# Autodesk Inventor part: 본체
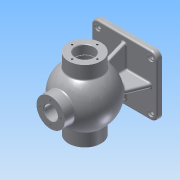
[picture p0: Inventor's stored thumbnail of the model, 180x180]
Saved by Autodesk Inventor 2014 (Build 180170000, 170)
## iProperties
Created: 2017-01
Part Number: 본체
Material: Aluminum 6061
Document SubType Name: Modeling
Designer: ksu
Density: 2.71 g/cm^3
Appearance: Aluminum - Flat
Mass: 1509 g
Surface Area: 1155.11 cm^2
Volume: 556.828 cm^3
Author: ksu
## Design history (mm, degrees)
sketch "Sketch1"
  geometry: L1 (-62.5, -57.5)-(62.5, -57.5); L2 (62.5, -57.5)-(62.5, 57.5); L3 (62.5, 57.5)-(-62.5, 57.5); L4 (-62.5, 57.5)-(-62.5, -57.5); L5 (-62.5, -57.5)-(62.5, 57.5); L6 (62.5, -57.5)-(-62.5, 57.5); 1 further point
  constraints: 12 end point, 2 midpoint, 2 parallel, 1 horizontal, 1 perpendicular
  dimensions: "d0" = 125 distance of L3.end L2.end; "d1" = 115 distance of L2.end L1.end
extrude "Extrusion1" new body sketch "Sketch1" distance "d2" = 10; taper "d3" = 0 deg
sketch "Sketch2"
  geometry: L1 (-57.5, 0)-(57.5, 0) reference; L2 (-68, 85)-(106.185, 85); L3 (-68, 116)-(-68, 102.5); L4 (68, 116)-(68, 102.5); L5 (-68, 116)-(-42.988, 116); L6 (42.988, 116)-(68, 116); L7 (-68, 102.5)-(-39.278, 102.5); L8 (39.278, 102.5)-(68, 102.5); A1 r 53 centre (0, 85) between (42.988, 116) and (-42.988, 116); A2 r 43 centre (0, 85) between (39.278, 102.5) and (-39.278, 102.5); 1 further point
  constraints: 14 end point, 6 parallel, 4 point on circle, 2 centre point, 1 coincident
  dimensions: "d4" = 106 diameter of A1; "d5" = 86 diameter of A2; "d6" = 85 distance from line of L1 A2.centre; "d9" = 136 distance of L3.start L4.start; "d10" = 68 horizontal distance of point (0, 0) L4.start; "d11" = 136 distance of L3.end L4.end; "d12" = 68 horizontal distance of point (0, 0) L4.end
revolve "Revolution1" sketch "Sketch2" stored, may be unused: angle "d13" = 90 deg
workplane "Work Plane1"
sketch "Sketch3"
  geometry: C1 r 27 at (0, 0); 1 further point
  constraints: 1 centre point, 1 coincident
  dimensions: "d15" = 54 diameter of C1
extrude "Extrusion2" join sketch "Sketch3" distance "d16" = 30; taper "d17" = 0 deg
sketch "Sketch4"
  geometry: C1 r 27 at (0, 0) reference; C2 r 13 at (0, 0)
  constraints: 1 centre point, 1 coincident
  dimensions: "d18" = 26 diameter of C2
extrude "Extrusion3" cut sketch "Sketch4" distance "d19" = 30; taper "d20" = 0 deg
sketch "Sketch5"
  geometry: L1 (62.5, 10)-(-62.5, 10) reference; L2 (-35.008, 53.295)-(-52.5, 10); L3 (35.008, 53.295)-(52.5, 10); L4 (-52.5, 10)-(52.5, 10); L5 (-62.5, 0)-(-62.5, 10) reference; L6 (62.5, 0)-(62.5, 10) reference; A1 r 47.231 centre (0, 85) between (-35.008, 53.295) and (35.008, 53.295); 3 further points
  constraints: 6 end point, 4 point on line, 2 point on circle, 1 centre point, 1 collinear
  dimensions: "d21" = 10 distance of L1.end L2.end; "d22" = 10 distance of L1.start L3.end; "d23" = 22 deg angle of L5 L2; "d24" = 22 deg angle of L6 L3
extrude "Extrusion4" join sketch "Sketch5" stored distance "d25" = 8; taper "d26" = 0 deg
sketch "Sketch6"
  geometry: L1 (57.5, 10)-(-57.5, 10) reference; L2 (-30.87, 51.162)-(-47.5, 10); L3 (30.87, 51.162)-(47.5, 10); L4 (-47.5, 10)-(47.5, 10); L5 (-57.5, 0)-(-57.5, 10) reference; L6 (57.5, 0)-(57.5, 10) reference; A1 r 45.804 centre (0, 85) between (-30.87, 51.162) and (30.87, 51.162); 1 further point
  constraints: 6 end point, 2 point on circle, 2 point on line, 1 centre point, 1 collinear
  dimensions: "d27" = 10 distance of L1.end L2.end; "d28" = 10 distance of L1.start L3.end; "d29" = 22 deg angle of L5 L2; "d30" = 22 deg angle of L6 L3
extrude "Extrusion5" join sketch "Sketch6" stored distance "d31" = 8; taper "d32" = 0 deg
fillet "Fillet1" dims "d33" = 12
sketch "Sketch7"
  geometry: A1 r 12 centre (-50.5, 45.5) between (-50.5, 57.5) and (-62.5, 45.5) reference; A2 r 12 centre (-50.5, -45.5) between (-62.5, -45.5) and (-50.5, -57.5) reference; A3 r 12 centre (50.5, -45.5) between (50.5, -57.5) and (62.5, -45.5) reference; A4 r 12 centre (50.5, 45.5) between (62.5, 45.5) and (50.5, 57.5) reference; 5 further points
  constraints: 4 coincident
hole "Hole1" sketch "Sketch7" at (-50.5, 45.5), (50.5, 45.5), (50.5, -45.5), (-50.5, -45.5) diameter "d34" = 8; stored, may be unused: countersink angle "d38" = 90 deg, drill point angle "d40" = 118 deg; dims "d35" = 6, "d36" = 12, "d37" = 3, "d39" = 10
sketch "Sketch8" dims "d41" = 45
  geometry: C1 r 31 at (0, 0) reference; 3 further points
  constraints: 1 coincident, 1 vertical alignment, 2 other
hole "Hole2" sketch "Sketch8" at (0, 22.5) diameter "d42" = 3.459; stored, may be unused: countersink angle "d46" = 90 deg, drill point angle "d48" = 118 deg; dims "d43" = 12, "d44" = 12, "d45" = 3, "d47" = 15
workaxis "Work Axis1"
pattern_circular "Circular Pattern1" dims angle "d50" = 360 deg
sketch "Sketch9" dims "d52" = 48
  geometry: C1 r 17.5 at (0, 0) reference; 3 further points
  constraints: 1 coincident, 1 vertical alignment, 2 other
hole "Hole3" sketch "Sketch9" at (0, 24) diameter "d53" = 3.459; stored, may be unused: countersink angle "d57" = 90 deg, drill point angle "d59" = 118 deg; dims "d54" = 16, "d55" = 12, "d56" = 3, "d58" = 19
pattern_circular "Circular Pattern2" dims angle "d61" = 360 deg
workplane "Work Plane2"
sketch "Sketch10"
  geometry: L1 (142.729, 66.239)-(142.729, 24.761); L2 (142.729, 24.761)-(137.271, 24.761); L3 (137.271, 24.761)-(137.271, 66.239); L4 (137.271, 66.239)-(142.729, 66.239); L5 (140, 66.239)-(140, 24.761); L6 (142.729, 45.5)-(137.271, 45.5); L7 (150, 72.5)-(130.607, 72.5) reference; 2 further points
  constraints: 5 midpoint, 4 end point, 2 other
  dimensions: "d64" = 27 distance from line of L7.start L6; "d97" = 10 horizontal distance of L7.start point (140, 45.5)
emboss "Emboss1" sketch "Sketch10" dims "d0" = 125, "d1" = 115, "d66" = 0.5, "d67" = 0
sketch "Sketch11"
  geometry: L1 (-27.094, 118.39)-(-27.094, 85); L2 (-27.094, 85)-(31.416, 85); L3 (31.416, 85)-(31.543, 114.224); L4 (-95.2, 85)-(95.2, 85) reference; A1 r 43 centre (0, 85) between (-24.98, 120) and (24.98, 120) reference; A2 r 43 centre (0, 85) between (31.543, 114.224) and (-27.094, 118.39); 1 further point
  constraints: 6 end point, 4 point on circle, 1 centre point, 1 coincident, 1 concentric, 1 perpendicular, 1 vertical
revolve "Revolution2" sketch "Sketch11" stored, may be unused: angle "d68" = 90 deg
chamfer "Chamfer1" distance "d69" = 1; stored, may be unused: second distance "d70" = 2, angle "d71" = 45 deg
sketch "Sketch12"
  geometry: L1 (50.25, 103.5)-(52, 103.5); L2 (52, 103.5)-(52, 85); L3 (52, 85)-(50.25, 85); L4 (50.25, 85)-(50.25, 103.5); L5 (45.5, 0)-(-45.5, 0) reference; L6 (68, 66.5)-(68, 103.5) reference; L7 (-95.2, 85)-(95.2, 85) reference; 1 further point
  constraints: 8 end point, 2 parallel, 1 horizontal, 1 perpendicular
  dimensions: "d72" = 85 distance between parallel lines of L5 L3; "d73" = 1.75 distance of L1.start L1.end; "d74" = 16 distance between parallel lines of L6 L2; "d76" = 18.5 distance between parallel lines of L3 L1
revolve "Revolution3" sketch "Sketch12" stored, may be unused: angle "d75" = 90 deg
sketch "Sketch13" dims "d77" = 40
  geometry: C1 r 27 at (0, 0) reference; 2 further points
  constraints: 1 coincident, 1 vertical alignment, 2 other
hole "Hole4" sketch "Sketch13" at (0, 20) diameter "d78" = 3.459; stored, may be unused: countersink angle "d82" = 90 deg, drill point angle "d84" = 118 deg; dims "d79" = 9, "d80" = 12, "d81" = 3, "d83" = 11
workaxis "Work Axis2"
pattern_circular "Circular Pattern3" dims angle "d86" = 360 deg
fillet "Fillet2" dims "d88" = 3
fillet "Fillet3" dims "d89" = 3
fillet "Fillet4" dims "d90" = 3
fillet "Fillet5" dims "d91" = 3
fillet "Fillet6" dims "d92" = 3
fillet "Fillet7" dims "d93" = 3
chamfer "Chamfer2" distance "d94" = 1; stored, may be unused: second distance "d95" = 2, angle "d96" = 45 deg
body "Solid1"
other parameters: "d7" = 62, "d8" = 35
